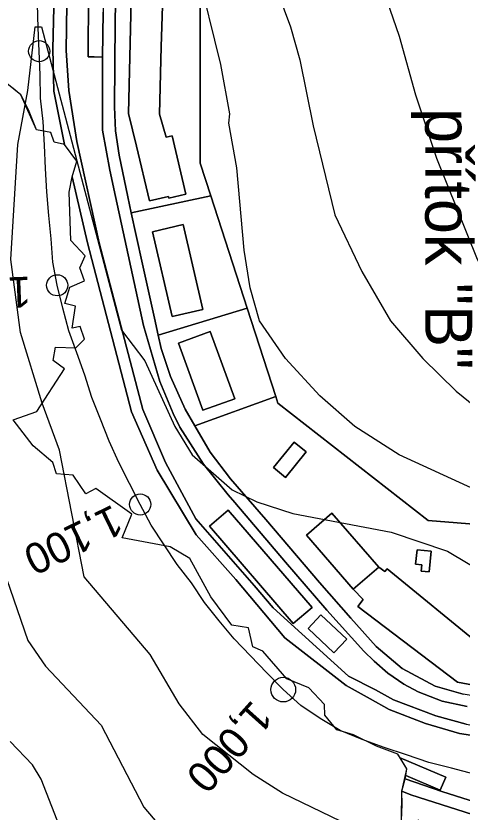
# Model space of a CAD drawing. Extents: x -510989 to -501240, y -1184665 to -1176089.
# Drawn here: x -505130.5 to -504940.6, y -1180268 to -1179929.3 of the extents above; entities that cross this region are included whole.
import ezdxf

# ---------------------------------------------------------------- set-up
doc = ezdxf.new("R2010")
doc.units = 0
for name, color, linetype in [('lesni_pozemek', 7, 'Continuous'), ('NAVRH_rozvodnice', 7, 'Continuous'), ('ostatni_plocha_x_draha', 7, 'Continuous'), ('ostatni_plocha_x_manipulacni_plocha', 7, 'Continuous'), ('ostatni_plocha_x_ostatni_komunikace', 7, 'Continuous'), ('popis', 7, 'Continuous'), ('trasovani_toku', 7, 'Continuous'), ('vrstevnice_01', 7, 'Continuous'), ('vrstevnice_02', 7, 'Continuous'), ('zastavena_plocha_a_nadvori', 7, 'Continuous')]:
    doc.layers.add(name, color=color, linetype=linetype)

msp = doc.modelspace()

# ---------------------------------------------------------------- linework, layer by layer
at = {"layer": 'lesni_pozemek'}
msp.add_lwpolyline([(-504918, -1180147), (-504955, -1180144), (-505019, -1180094.01), (-505019.81, -1180091.25), (-505032.06, -1180053.63), (-505047.54, -1180005.79), (-505052, -1179992.01), (-505052, -1179892.01)], dxfattribs=at)
at = {"layer": 'ostatni_plocha_x_draha'}
for points in [[(-504783.83, -1180274.01), (-504828.03, -1180261.36), (-504846.92, -1180255.69), (-504876.7, -1180246.93), (-504903.53, -1180240.42), (-504941.73, -1180234.59), (-504956.19, -1180230.36), (-504971.65, -1180224.34), (-504979.7, -1180219.93), (-504989.9, -1180214.14), (-505016.08, -1180193.98), (-505036.83, -1180169.08), (-505053.71, -1180150.09), (-505070.44, -1180122.64), (-505081.27, -1180097.73), (-505100.02, -1180025.78), (-505106.57, -1179997.77), (-505104.55, -1179991.12), (-505109.78, -1179984.04), (-505114.35, -1179961.35), (-505114.78, -1179943.24), (-505113.43, -1179884.33)], [(-505108.21, -1179884.39), (-505109.11, -1179944.05), (-505107.94, -1179961.1), (-505104.63, -1179982.76), (-505094.99, -1180025.84), (-505076.48, -1180096.77), (-505066.83, -1180119.31), (-505053.9, -1180143.25), (-505029.13, -1180171.63), (-505021.04, -1180181.1), (-504988.93, -1180210.17), (-504977.51, -1180216.02), (-504969.72, -1180220.33), (-504951.76, -1180227.06), (-504938.88, -1180230.67), (-504916.82, -1180234.67), (-504902.88, -1180236.87), (-504869.49, -1180244.27), (-504844.53, -1180250.25), (-504824.88, -1180254.78), (-504808.63, -1180258.13), (-504782.52, -1180265.23), (-504776.08, -1180267.21), (-504770.12, -1180269.04)]]:
    msp.add_lwpolyline(points, dxfattribs=at)
at = {"layer": 'ostatni_plocha_x_manipulacni_plocha'}
for points in [[(-505143.19, -1179883.43), (-505122.13, -1179883.47), (-505115.41, -1179883.03), (-505118.11, -1179844.74), (-505113, -1179844.94), (-505112.92, -1179850.19), (-505113.43, -1179884.33), (-505114.78, -1179943.24), (-505114.35, -1179961.35), (-505109.78, -1179984.04), (-505114.26, -1179983.01), (-505115.57, -1179978.96), (-505121.67, -1179977.73), (-505125.17, -1179969.2), (-505128.45, -1179962.86), (-505132.44, -1179959.6)], [(-504938.88, -1180230.67), (-504951.76, -1180227.06), (-504969.72, -1180220.33), (-504977.51, -1180216.02), (-504988.93, -1180210.17), (-505021.04, -1180181.1), (-505029.13, -1180171.63), (-505053.9, -1180143.25), (-505066.83, -1180119.31), (-505076.48, -1180096.77), (-505094.99, -1180025.84), (-505104.63, -1179982.76), (-505107.94, -1179961.1), (-505109.11, -1179944.05), (-505108.21, -1179884.39)], [(-505099.47, -1179919.58), (-505099.7, -1179937.93), (-505099.76, -1179946.77), (-505099.35, -1179946.73), (-505097.21, -1179946.75), (-505093.64, -1179946.89), (-505093.62, -1179963.44), (-505093.6, -1179977.95), (-505090.51, -1179994.97), (-505088.1, -1180006.15), (-505076.2, -1180061.03), (-505069.27, -1180084.88), (-505063.54, -1180098.53), (-505060.66, -1180104.33), (-505050.65, -1180119.97), (-505040.2, -1180133.06), (-505037.36, -1180136.4), (-505015.76, -1180161.71), (-504998.1, -1180182.19), (-504982.35, -1180199.55), (-504978.04, -1180203.91), (-504972.19, -1180208.88), (-504965.32, -1180213.56), (-504959.24, -1180216.87), (-504949.09, -1180220.84), (-504938.47, -1180223.07)], [(-504908.55, -1180272.17), (-504949.19, -1180259.33), (-504964.78, -1180253.85), (-504964.59, -1180252.53), (-504949.95, -1180258.73), (-504947.49, -1180253.21), (-504966.91, -1180244.99), (-504967.88, -1180243.36), (-504977.05, -1180239.94), (-504986.77, -1180235.22), (-504993.9, -1180232.99), (-504998.94, -1180226.84), (-504999.09, -1180222.25), (-505005.76, -1180215.25), (-505015.22, -1180211.31), (-505025.35, -1180199.55), (-505029.64, -1180197.74), (-505031.54, -1180189.66), (-505038.6, -1180188.46), (-505047.46, -1180176.43), (-505056.48, -1180160.09), (-505064.84, -1180155.13), (-505085.26, -1180151.32), (-505081.09, -1180141.3), (-505096.45, -1180130.36), (-505100.72, -1180132.61), (-505106.17, -1180124.76), (-505113.27, -1180124.16), (-505114.8, -1180119.29), (-505123.22, -1180112.29), (-505131.64, -1180101.21), (-505121.64, -1180097.55), (-505109.88, -1180079.39), (-505114.58, -1180075.9), (-505113.71, -1180070.21), (-505104.97, -1180070.58), (-505101.26, -1180066.86), (-505103.11, -1180061.5), (-505106.61, -1180062.15), (-505105.08, -1180052.75), (-505109.67, -1180051.65), (-505107.49, -1180044.65), (-505101.26, -1180042.03), (-505103.22, -1180036.45), (-505101.04, -1180031.31), (-505107.05, -1180024.86), (-505107.82, -1180004.3), (-505106.57, -1179997.77), (-505100.02, -1180025.78), (-505081.27, -1180097.73), (-505070.44, -1180122.64), (-505053.71, -1180150.09), (-505036.83, -1180169.08), (-505016.08, -1180193.98), (-504989.9, -1180214.14), (-504979.7, -1180219.93), (-504971.65, -1180224.34), (-504956.19, -1180230.36), (-504941.73, -1180234.59), (-504903.53, -1180240.42)], [(-504582.19, -1180712.85), (-504632.07, -1180660.99), (-504665.33, -1180626.68), (-504679.28, -1180612.3), (-504715.1, -1180575.1), (-504748, -1180544.2), (-504783.19, -1180511.92), (-504876.41, -1180425.21), (-504990.84, -1180318.68), (-504980.27, -1180301.58), (-504971.38, -1180284.92), (-504966.39, -1180271.5), (-504966.07, -1180264.78), (-504966.25, -1180259.12), (-504962.42, -1180260.76), (-504936.2, -1180269.1), (-504900.44, -1180279.57), (-504868.02, -1180289), (-504802.18, -1180310.29), (-504812.19, -1180333.2), (-504959.28, -1180271.5), (-504976, -1180300.73), (-504610.6, -1180648.46)]]:
    msp.add_lwpolyline(points, dxfattribs=at)
for points in [[(-505087.26, -1179872.27), (-505059.99, -1179872.19), (-505057.46, -1179877.6), (-505052, -1179892.01), (-505052, -1179992.01), (-505047.54, -1180005.79), (-505081.4, -1180013.13), (-505082.92, -1180006.29), (-505086.53, -1179988.51), (-505088.16, -1179978.17), (-505088.55, -1179968.01), (-505088.32, -1179931.96), (-505087.28, -1179874.31)], [(-505080.35, -1179874.43), (-505082.52, -1179970.82), (-505079.22, -1179984.67), (-505073.66, -1180008), (-505065.55, -1180006.15), (-505065.36, -1180006.8), (-505058.22, -1180005.14), (-505063.98, -1179980.35), (-505066.57, -1179980.95), (-505069.42, -1179971.16), (-505068.6, -1179942.37), (-505068.48, -1179938.22), (-505067.73, -1179911.68), (-505062.03, -1179911.81), (-505061.2, -1179874.86)], [(-505099.47, -1179919.58), (-505096.32, -1179919.49), (-505093.34, -1179919.6), (-505093.35, -1179927.7), (-505093.64, -1179946.89), (-505097.21, -1179946.75), (-505099.35, -1179946.73), (-505099.76, -1179946.77), (-505099.7, -1179937.93)], [(-505081.4, -1180013.13), (-505047.54, -1180005.79), (-505032.06, -1180053.63), (-505069.89, -1180065.1), (-505071.52, -1180057.92), (-505076.65, -1180034.94), (-505079.28, -1180022.73)], [(-505072.39, -1180021.15), (-505063.98, -1180057.24), (-505050.88, -1180054.19), (-505059.29, -1180018.1)], [(-505069.89, -1180065.1), (-505032.06, -1180053.63), (-505019.81, -1180091.25), (-505054.3, -1180103.66), (-505058.44, -1180096.57), (-505064.66, -1180082.67), (-505068.6, -1180070.76)], [(-505061.29, -1180068.51), (-505050.93, -1180097.07), (-505037.38, -1180092.16), (-505047.75, -1180063.6)], [(-505019, -1180094.01), (-504955, -1180144), (-504918, -1180147), (-504918, -1180184), (-504850.17, -1180191.73), (-504857.56, -1180232.7), (-504873.44, -1180229.37), (-504914.1, -1180222.25), (-504940.12, -1180217.84), (-504951.99, -1180214.49), (-504966.02, -1180206.92), (-504977.12, -1180197.61), (-504987.89, -1180185.55), (-505001.31, -1180170.44), (-505024.15, -1180143.5), (-505039.13, -1180126.23), (-505047.75, -1180114.86), (-505054.3, -1180103.66), (-505019.81, -1180091.25)], [(-505012.08, -1180110.65), (-505020.9, -1180121.48), (-505015.78, -1180125.65), (-505006.96, -1180114.81)], [(-505040.12, -1180139.58), (-505048.1, -1180146.44), (-505012.46, -1180187.84), (-505004.46, -1180180.96)], [(-505006.84, -1180150.23), (-504986.9, -1180173.23), (-504982.63, -1180177.55), (-504985.02, -1180180.63), (-504942.51, -1180212.83), (-504935.67, -1180214.08), (-504935.73, -1180214.36), (-504873.66, -1180225.5), (-504870.58, -1180208.35), (-504932.65, -1180197.21), (-504972.54, -1180164.55), (-504973.46, -1180165.74), (-504976, -1180163.78), (-504995.97, -1180140.83)], [(-504959.76, -1180156.41), (-504960.37, -1180162.57), (-504957.78, -1180162.82), (-504958.05, -1180165.49), (-504954.57, -1180165.83), (-504953.7, -1180157)], [(-505000.64, -1180184.08), (-505006.13, -1180189.9), (-504995.15, -1180200.24), (-504989.67, -1180194.42)]]:
    msp.add_lwpolyline(points, close=True, dxfattribs=at)
at = {"layer": 'ostatni_plocha_x_ostatni_komunikace'}
for points in [[(-505087.28, -1179874.31), (-505088.32, -1179931.96), (-505088.55, -1179968.01), (-505088.16, -1179978.17), (-505086.53, -1179988.51), (-505082.92, -1180006.29), (-505081.4, -1180013.13), (-505079.28, -1180022.73), (-505076.65, -1180034.94), (-505071.52, -1180057.92), (-505069.89, -1180065.1), (-505068.6, -1180070.76), (-505064.66, -1180082.67), (-505058.44, -1180096.57), (-505054.3, -1180103.66), (-505047.75, -1180114.86), (-505039.13, -1180126.23), (-505024.15, -1180143.5), (-505001.31, -1180170.44), (-504987.89, -1180185.55), (-504977.12, -1180197.61), (-504966.02, -1180206.92), (-504951.99, -1180214.49), (-504940.12, -1180217.84)], [(-504938.47, -1180223.07), (-504949.09, -1180220.84), (-504959.24, -1180216.87), (-504965.32, -1180213.56), (-504972.19, -1180208.88), (-504978.04, -1180203.91), (-504982.35, -1180199.55), (-504998.1, -1180182.19), (-505015.76, -1180161.71), (-505037.36, -1180136.4), (-505040.2, -1180133.06), (-505050.65, -1180119.97), (-505060.66, -1180104.33), (-505063.54, -1180098.53), (-505069.27, -1180084.88), (-505076.2, -1180061.03), (-505088.1, -1180006.15), (-505090.51, -1179994.97), (-505093.6, -1179977.95), (-505093.62, -1179963.44), (-505093.64, -1179946.89), (-505093.35, -1179927.7)], [(-504936.2, -1180269.1), (-504962.42, -1180260.76), (-504966.25, -1180259.12), (-504964.78, -1180253.85), (-504949.19, -1180259.33), (-504908.55, -1180272.17)]]:
    msp.add_lwpolyline(points, dxfattribs=at)
at = {"layer": 'popis'}
msp.add_lwpolyline([(-504966.39, -1180271.5), (-504966.25, -1180259.12), (-504964.38, -1180251.06), (-504964.17, -1180249.59), (-504967.88, -1180243.36), (-504977.05, -1180239.94), (-504986.77, -1180235.22), (-504993.9, -1180232.99), (-504998.94, -1180226.84), (-504999.09, -1180222.25), (-505005.76, -1180215.25), (-505015.22, -1180211.31), (-505025.35, -1180199.55), (-505029.64, -1180197.74), (-505031.54, -1180189.66), (-505038.6, -1180188.46), (-505047.46, -1180176.43), (-505056.48, -1180160.09), (-505064.84, -1180155.13), (-505085.26, -1180151.32), (-505081.09, -1180141.3), (-505096.45, -1180130.36), (-505100.72, -1180132.61), (-505106.17, -1180124.76), (-505113.27, -1180124.16), (-505114.8, -1180119.29), (-505123.22, -1180112.29), (-505131.64, -1180101.21), (-505121.64, -1180097.55), (-505109.88, -1180079.39), (-505114.58, -1180075.9), (-505113.71, -1180070.21), (-505104.97, -1180070.58), (-505101.26, -1180066.86), (-505103.11, -1180061.5), (-505106.61, -1180062.15), (-505105.08, -1180052.75), (-505109.67, -1180051.65), (-505107.49, -1180044.65), (-505101.26, -1180042.03), (-505103.22, -1180036.45), (-505101.04, -1180031.31), (-505107.05, -1180024.86), (-505107.82, -1180004.3), (-505106.57, -1179997.77), (-505104.55, -1179991.12), (-505109.78, -1179984.04), (-505114.26, -1179983.01), (-505115.57, -1179978.96), (-505121.67, -1179977.73), (-505128.45, -1179962.86), (-505135.01, -1179957.5)], dxfattribs=at)
at = {"layer": 'trasovani_toku'}
for p, q in [((-505120.98, -1179934.33), (-505121.35, -1179924.33)), ((-505120.6, -1179944.32), (-505120.98, -1179934.33)), ((-505120.17, -1179954.31), (-505120.6, -1179944.32)), ((-505119.99, -1179964.31), (-505120.17, -1179954.31)), ((-505118.85, -1179974.24), (-505119.99, -1179964.31)), ((-505118.35, -1179984.23), (-505118.85, -1179974.24)), ((-505117.89, -1179994.22), (-505118.35, -1179984.23)), ((-505117.39, -1180004.21), (-505117.89, -1179994.22)), ((-505116.52, -1180014.17), (-505117.39, -1180004.21)), ((-505115.44, -1180024.11), (-505116.52, -1180014.17)), ((-505114.75, -1180034.09), (-505115.44, -1180024.11)), ((-505112.92, -1180043.92), (-505114.75, -1180034.09)), ((-505110.5, -1180053.62), (-505112.92, -1180043.92)), ((-505108.01, -1180063.31), (-505110.5, -1180053.62)), ((-505104.55, -1180072.69), (-505108.01, -1180063.31)), ((-505101.18, -1180082.1), (-505104.55, -1180072.69)), ((-505098.15, -1180091.63), (-505101.18, -1180082.1)), ((-505094.47, -1180100.93), (-505098.15, -1180091.63)), ((-505090.78, -1180110.22), (-505094.47, -1180100.93)), ((-505086.67, -1180119.34), (-505090.78, -1180110.22)), ((-505082.17, -1180128.27), (-505086.67, -1180119.34)), ((-505077.59, -1180137.16), (-505082.17, -1180128.27)), ((-505072.97, -1180146.03), (-505077.59, -1180137.16)), ((-505067.4, -1180154.34), (-505072.97, -1180146.03)), ((-505061.91, -1180162.69), (-505067.4, -1180154.34)), ((-505055.76, -1180170.58), (-505061.91, -1180162.69)), ((-505050.18, -1180178.88), (-505055.76, -1180170.58)), ((-505043.96, -1180186.7), (-505050.18, -1180178.88)), ((-505037.54, -1180194.37), (-505043.96, -1180186.7)), ((-505030.64, -1180201.61), (-505037.54, -1180194.37)), ((-505023.74, -1180208.85), (-505030.64, -1180201.61)), ((-505016.7, -1180215.95), (-505023.74, -1180208.85)), ((-505009.28, -1180222.66), (-505016.7, -1180215.95)), ((-505000.99, -1180228.25), (-505009.28, -1180222.66)), ((-504992.41, -1180233.39), (-505000.99, -1180228.25)), ((-504983.12, -1180237.1), (-504992.41, -1180233.39)), ((-504973.74, -1180240.55), (-504983.12, -1180237.1)), ((-504964.26, -1180243.74), (-504973.74, -1180240.55)), ((-504954.78, -1180246.93), (-504964.26, -1180243.74)), ((-504945.08, -1180249.35), (-504954.78, -1180246.93)), ((-504935.43, -1180251.98), (-504945.08, -1180249.35))]:
    msp.add_line(p, q, dxfattribs=at)
for centre, radius in [((-505120.6, -1179944.32), 4.5), ((-505112.92, -1180043.92), 4.5), ((-505077.59, -1180137.16), 4.5), ((-505016.7, -1180215.95), 5.25)]:
    msp.add_circle(centre, radius, dxfattribs=at)
at = {"layer": 'vrstevnice_01'}
for points in [[(-504934.81, -1180131), (-504967.41, -1180116), (-504986.19, -1180104), (-505001.19, -1180091), (-505015.81, -1180075), (-505026.81, -1180059), (-505030.81, -1180045), (-505033.31, -1180029), (-505036.41, -1179994), (-505039.91, -1179975), (-505039.5, -1179971), (-505043.31, -1179950), (-505053.31, -1179909)], [(-504600.09, -1180235), (-504637.31, -1180214), (-504678.59, -1180194), (-504694.09, -1180185), (-504706, -1180177), (-504738.81, -1180148), (-504759.81, -1180134), (-504778.41, -1180126), (-504788.81, -1180122), (-504849.91, -1180109), (-504863, -1180104), (-504889.5, -1180089), (-504896.31, -1180085), (-504912.81, -1180068), (-504923.91, -1180052), (-504934.09, -1180033), (-504951.31, -1179990), (-504960.31, -1179963), (-504967.19, -1179938), (-504973.81, -1179919)], [(-505200.69, -1179952), (-505198.41, -1179968), (-505196, -1179976), (-505193.31, -1180001), (-505194.5, -1180026), (-505202.31, -1180059), (-505204.59, -1180065), (-505205.5, -1180077), (-505202.59, -1180083), (-505172.09, -1180106), (-505162.19, -1180117), (-505152.31, -1180132), (-505137.69, -1180160), (-505125.41, -1180195), (-505117.91, -1180206), (-505094.19, -1180231), (-505076, -1180266), (-505063.31, -1180281)]]:
    msp.add_lwpolyline(points, dxfattribs=at)
at = {"layer": 'vrstevnice_02'}
for points in [[(-505022.19, -1179911), (-505013.59, -1179934), (-505009.59, -1179948), (-505004, -1179976), (-504994.81, -1180014), (-504983.31, -1180038), (-504971.09, -1180059), (-504957.31, -1180075), (-504943.09, -1180089), (-504918.41, -1180109), (-504909, -1180115), (-504893.19, -1180123), (-504875.19, -1180128), (-504832.69, -1180136), (-504816.09, -1180137), (-504793.69, -1180142), (-504771.69, -1180150), (-504734.81, -1180171), (-504687.69, -1180202), (-504673.19, -1180210), (-504652.69, -1180218), (-504634.5, -1180227), (-504608.5, -1180241)], [(-504992, -1180272), (-505017, -1180260), (-505029.5, -1180252), (-505050.91, -1180235), (-505061, -1180222), (-505073.31, -1180201), (-505101.41, -1180168), (-505111.91, -1180114), (-505119.31, -1180094), (-505128.5, -1180064), (-505132.59, -1180033), (-505129.69, -1179984), (-505125.41, -1179961), (-505122.31, -1179934), (-505119.59, -1179934), (-505085.59, -1180063), (-505075.69, -1180076), (-505062.91, -1180104), (-505055.41, -1180116), (-505038.41, -1180131), (-505027.91, -1180136), (-505012.69, -1180141), (-504970.81, -1180149), (-504946.81, -1180157), (-504888, -1180192)], [(-505106.09, -1180289), (-505119.81, -1180254), (-505123.5, -1180248), (-505132.91, -1180238)]]:
    msp.add_lwpolyline(points, dxfattribs=at)
at = {"layer": 'zastavena_plocha_a_nadvori'}
for points in [[(-505080.35, -1179874.43), (-505061.2, -1179874.86), (-505062.03, -1179911.81), (-505067.73, -1179911.68), (-505068.48, -1179938.22), (-505068.6, -1179942.37), (-505069.42, -1179971.16), (-505066.57, -1179980.95), (-505063.98, -1179980.35), (-505058.22, -1180005.14), (-505065.36, -1180006.8), (-505065.55, -1180006.15), (-505073.66, -1180008), (-505079.22, -1179984.67), (-505082.52, -1179970.82)], [(-505072.39, -1180021.15), (-505059.29, -1180018.1), (-505050.88, -1180054.19), (-505063.98, -1180057.24)], [(-505061.29, -1180068.51), (-505047.75, -1180063.6), (-505037.38, -1180092.16), (-505050.93, -1180097.07)], [(-505012.08, -1180110.65), (-505006.96, -1180114.81), (-505015.78, -1180125.65), (-505020.9, -1180121.48)], [(-505040.12, -1180139.58), (-505004.46, -1180180.96), (-505012.46, -1180187.84), (-505048.1, -1180146.44)], [(-505006.84, -1180150.23), (-504995.97, -1180140.83), (-504976, -1180163.78), (-504986.9, -1180173.23)], [(-504959.76, -1180156.41), (-504953.7, -1180157), (-504954.57, -1180165.83), (-504958.05, -1180165.49), (-504957.78, -1180162.82), (-504960.37, -1180162.57)], [(-504973.46, -1180165.74), (-504972.54, -1180164.55), (-504932.65, -1180197.21), (-504935.67, -1180214.08), (-504942.51, -1180212.83), (-504985.02, -1180180.63), (-504982.63, -1180177.55), (-504986.9, -1180173.23), (-504976, -1180163.78)], [(-505000.64, -1180184.08), (-504989.67, -1180194.42), (-504995.15, -1180200.24), (-505006.13, -1180189.9)], [(-504964.17, -1180249.59), (-504966.91, -1180244.99), (-504947.49, -1180253.21), (-504949.95, -1180258.73), (-504964.59, -1180252.53)]]:
    msp.add_lwpolyline(points, close=True, dxfattribs=at)

# ---------------------------------------------------------------- texts
at = {"layer": 'NAVRH_rozvodnice'}
msp.add_text('přítok "B"', height=20, rotation=270, dxfattribs=at).set_placement((-504956.26, -1179968.54))
at = {"layer": 'trasovani_toku'}
for s, rotation, p in [('1,200', 182.1077, (-505124.31, -1180040.2)), ('1,100', 205.9618, (-505089.24, -1180136.97)), ('1,000', 228.2185, (-505029.87, -1180219.86))]:
    msp.add_text(s, height=13, rotation=rotation, dxfattribs=at).set_placement(p)

doc.saveas('drawing.dxf')
